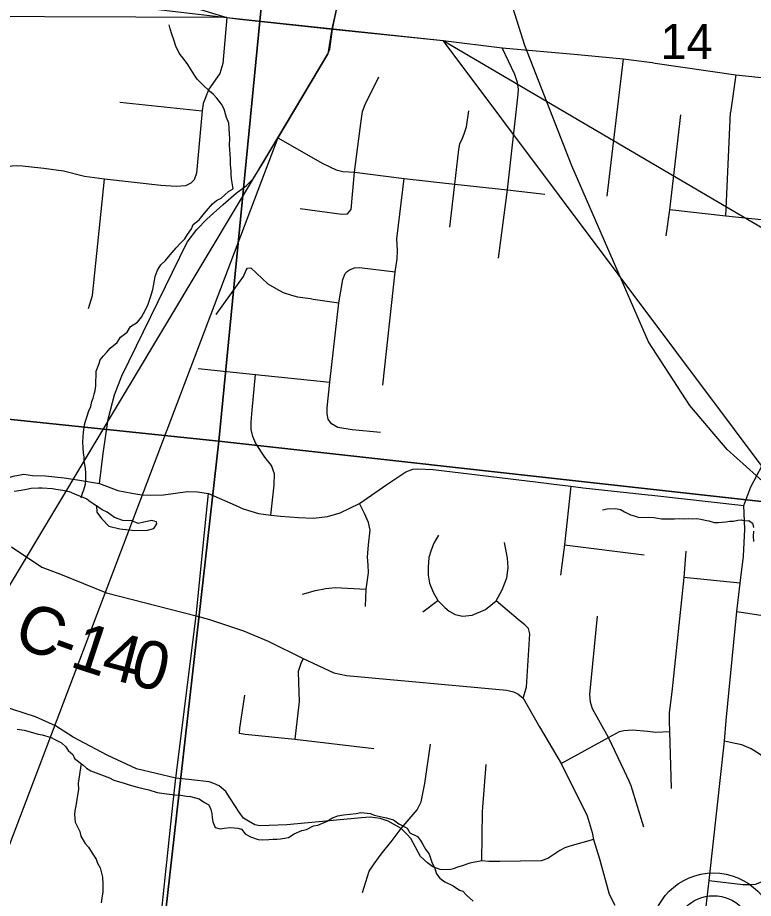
# Model space of a CAD drawing. Extents: x 0 to 34, y 0 to 22.
# Drawn here: x 6.604 to 7.479, y 17.836 to 18.884 of the extents above; entities that cross this region are included whole.
import ezdxf

# ---------------------------------------------------------------- set-up
doc = ezdxf.new("R2010")
doc.units = 0
for name, color, linetype in [('GM_X_City_Street', 7, 'Continuous'), ('GM_X_Corporation', 7, 'Continuous'), ('GM_X_County_Road', 7, 'Continuous'), ('GM_X_County_Road_Text', 7, 'Continuous'), ('GM_X_Minor_Lake', 7, 'Continuous'), ('GM_X_Minor_River', 7, 'Continuous'), ('GM_X_Rail_Line', 7, 'Continuous'), ('GM_X_Section_Text', 7, 'Continuous'), ('GM_X_Township_Road', 7, 'Continuous'), ('GM_X_Unincorporated', 7, 'Continuous'), ('SH_Text', 7, 'Continuous')]:
    doc.layers.add(name, color=color, linetype=linetype)

msp = doc.modelspace()

# ---------------------------------------------------------------- linework, layer by layer
at = {"layer": 'GM_X_City_Street'}
msp.add_line((7.4583, 18.8156), (7.4518, 18.7707), dxfattribs=at)
at = {"layer": 'GM_X_Corporation'}
for points in [[(5.9616, 19.4927), (6.9413, 19.3834), (6.8431, 18.3799), (5.8893, 18.4792)], [(7.955, 19.3167), (7.9506, 19.2737), (7.8526, 18.2675), (6.8431, 18.3799), (6.9413, 19.3834), (7.3067, 19.3446), (7.3077, 19.388)], [(6.8431, 18.3799), (6.7271, 17.3517), (5.7989, 17.4561), (5.8893, 18.4792)], [(6.8431, 18.3799), (7.8526, 18.2675), (7.7575, 17.2431), (6.7271, 17.3517)]]:
    msp.add_lwpolyline(points, close=True, dxfattribs=at)
at = {"layer": 'GM_X_County_Road'}
for points in [[(6.2648, 18.9452), (6.2762, 18.9441), (6.4455, 18.9279), (6.51, 18.9217), (6.5147, 18.9212), (6.6008, 18.9124), (6.6536, 18.9063), (6.701, 18.9016), (6.7946, 18.8905), (6.8528, 18.8836), (6.8619, 18.8825)], [(6.9786, 18.8699), (6.9921, 18.934), (6.9936, 18.9529)], [(6.8619, 18.8825), (6.8683, 18.8818), (6.9786, 18.8699)], [(6.7012, 18.3295), (6.7057, 18.3652), (6.7115, 18.4061), (6.7189, 18.4349), (6.7276, 18.4573), (6.8057, 18.6164), (6.8169, 18.6316), (6.829, 18.6437), (6.8485, 18.6613), (6.8638, 18.6749), (6.8758, 18.6836), (6.884, 18.6917), (6.8964, 18.7118), (6.9134, 18.7405), (6.9727, 18.8404), (6.9751, 18.846), (6.9786, 18.8699)], [(6.9786, 18.8699), (7.1101, 18.8565), (7.1805, 18.8478), (7.2702, 18.8398), (7.3244, 18.8344), (7.3587, 18.8301), (7.3625, 18.8296)], [(7.3625, 18.8296), (7.4583, 18.8156), (7.5834, 18.8023), (7.5901, 18.8016), (7.6544, 18.7948)], [(7.4678, 18.3034), (7.4763, 18.3256), (7.4897, 18.3507), (7.4923, 18.3553), (7.5228, 18.4144)], [(6.8309, 18.3175), (6.8627, 18.3036), (6.8723, 18.2993), (6.8902, 18.2939), (6.9051, 18.2918), (6.9167, 18.2904), (6.9378, 18.2889), (6.9557, 18.2881), (6.9725, 18.2901), (6.9877, 18.2946), (7.0104, 18.3055), (7.0431, 18.3284), (7.0656, 18.3432), (7.0741, 18.3464), (7.0794, 18.347), (7.0983, 18.346), (7.2329, 18.3296)], [(6.5051, 18.295), (6.5635, 18.3256), (6.584, 18.3334), (6.5984, 18.3381), (6.6113, 18.3404), (6.6216, 18.339), (6.6371, 18.3387), (6.6592, 18.3361), (6.6751, 18.3338), (6.7012, 18.3295)], [(6.7012, 18.3295), (6.7231, 18.3211), (6.7397, 18.3178), (6.7514, 18.3161), (6.7624, 18.3154), (6.7775, 18.3161), (6.8058, 18.3198), (6.8179, 18.3196), (6.8309, 18.3175)], [(7.2329, 18.3296), (7.2387, 18.3289), (7.262, 18.3261), (7.2766, 18.3243), (7.3541, 18.3158)], [(6.755, 17.6085), (6.7645, 17.693), (6.7721, 17.7924), (6.7884, 17.9468), (6.7919, 17.9787), (6.8164, 18.1721), (6.8285, 18.2944), (6.8309, 18.3175)], [(7.3541, 18.3158), (7.3582, 18.3154), (7.4678, 18.3034)], [(7.4132, 17.5855), (7.4215, 17.6597), (7.4203, 17.7001), (7.4178, 17.7283), (7.4167, 17.7471), (7.4194, 17.7953), (7.4265, 17.857), (7.4448, 18.0229), (7.4467, 18.0474), (7.4597, 18.177), (7.4634, 18.2109), (7.4675, 18.2429), (7.469, 18.2749), (7.4678, 18.3034)], [(6.5963, 18.2539), (6.6325, 18.2298), (6.6546, 18.2214), (6.7095, 18.1993), (6.8164, 18.1721), (6.8321, 18.1677), (6.8724, 18.154), (6.902, 18.142), (6.9436, 18.1213), (6.9801, 18.104), (6.9951, 18.1009), (7.186, 18.0837), (7.1939, 18.0817), (7.1991, 18.079), (7.2053, 18.0741), (7.2249, 18.0398), (7.2504, 17.9963), (7.2813, 17.9341), (7.2875, 17.9142), (7.289, 17.9061), (7.296, 17.8829), (7.3076, 17.8408), (7.3144, 17.8278)]]:
    msp.add_lwpolyline(points, dxfattribs=at)
at = {"layer": 'GM_X_Minor_Lake'}
for points in [[(6.6976, 18.3028), (6.6979, 18.2954), (6.7034, 18.2877), (6.7123, 18.2787), (6.7255, 18.2753), (6.7433, 18.2733), (6.7585, 18.274), (6.7658, 18.2758), (6.7694, 18.2814), (6.769, 18.2836), (6.7634, 18.2853), (6.7538, 18.2833)], [(6.7538, 18.2833), (6.7473, 18.2819), (6.7398, 18.2848), (6.7288, 18.2855), (6.719, 18.2888), (6.7104, 18.2951), (6.7044, 18.2979), (6.6976, 18.3028)]]:
    msp.add_lwpolyline(points, dxfattribs=at)
at = {"layer": 'GM_X_Minor_River'}
for points in [[(6.8583, 18.692), (6.8578, 18.697), (6.8579, 18.7012), (6.857, 18.7084), (6.8572, 18.7149), (6.8567, 18.7217), (6.8561, 18.7263), (6.8559, 18.7324), (6.8562, 18.7396), (6.856, 18.745), (6.8555, 18.7518), (6.8549, 18.7579), (6.8525, 18.7648), (6.8494, 18.7745), (6.8462, 18.7807), (6.8408, 18.7877), (6.8364, 18.7924), (6.8319, 18.796), (6.8242, 18.8038), (6.8176, 18.8105), (6.8144, 18.8152), (6.8104, 18.8214), (6.8054, 18.8292), (6.8003, 18.8358), (6.7959, 18.8413), (6.792, 18.8498), (6.7896, 18.8571), (6.7872, 18.864), (6.7851, 18.8702), (6.784, 18.875)], [(6.6793, 18.3124), (6.681, 18.3177), (6.6827, 18.3218), (6.6844, 18.3286), (6.6851, 18.3358), (6.6849, 18.3411), (6.6847, 18.3476), (6.6831, 18.356), (6.6829, 18.361), (6.6823, 18.3655), (6.6818, 18.3724), (6.6812, 18.3785), (6.6818, 18.3849), (6.682, 18.3903), (6.6834, 18.3993), (6.6847, 18.4035), (6.686, 18.4084), (6.6886, 18.4159), (6.6907, 18.4211), (6.692, 18.4268), (6.6937, 18.4309), (6.695, 18.4358), (6.6959, 18.44), (6.6968, 18.4456), (6.6974, 18.4631), (6.7008, 18.4721), (6.7021, 18.4766), (6.706, 18.4814), (6.71, 18.4855), (6.7139, 18.4903), (6.7221, 18.4972), (6.7262, 18.5035), (6.7343, 18.5093), (6.738, 18.516), (6.7465, 18.5214), (6.7513, 18.5274), (6.7558, 18.536), (6.759, 18.5427), (6.762, 18.5509), (6.7646, 18.56), (6.7659, 18.5664), (6.7665, 18.5709), (6.7674, 18.5755), (6.7703, 18.5833), (6.7743, 18.5897), (6.7798, 18.5948), (6.7834, 18.5989), (6.7877, 18.604), (6.7925, 18.6099), (6.7972, 18.6147), (6.8027, 18.6206), (6.8059, 18.6254), (6.8107, 18.6325), (6.8128, 18.6374), (6.8198, 18.6432), (6.8262, 18.651), (6.8357, 18.662), (6.8404, 18.6661), (6.8458, 18.6689), (6.8505, 18.6729), (6.8548, 18.6766), (6.8602, 18.6798), (6.8583, 18.692)], [(6.5998, 18.3201), (6.6079, 18.3214), (6.6144, 18.3227), (6.6197, 18.324), (6.6288, 18.3244), (6.633, 18.3243), (6.6451, 18.3235), (6.6493, 18.3226), (6.6576, 18.3215), (6.6651, 18.3198), (6.6741, 18.316), (6.6812, 18.3131), (6.6861, 18.3111), (6.6902, 18.3079), (6.6957, 18.3043), (6.6976, 18.3028)], [(7.2995, 18.2982), (7.3052, 18.2992), (7.3151, 18.2997), (7.3211, 18.2984), (7.326, 18.2956), (7.3331, 18.2923), (7.3373, 18.291), (7.3422, 18.2894), (7.3608, 18.2889), (7.3657, 18.2883), (7.3699, 18.2875), (7.3764, 18.2873), (7.3855, 18.2874), (7.3912, 18.2876), (7.3977, 18.2875), (7.4019, 18.2877), (7.4068, 18.2872), (7.4117, 18.2878), (7.4167, 18.2869), (7.422, 18.2856), (7.4261, 18.2848), (7.4325, 18.2831), (7.4375, 18.2829), (7.442, 18.2835), (7.4466, 18.2838), (7.4512, 18.2844), (7.4554, 18.2847), (7.4607, 18.2857), (7.4649, 18.2863), (7.4691, 18.2851), (7.4737, 18.2853), (7.4781, 18.2822), (7.4795, 18.2772)], [(7.4794, 18.2726), (7.4789, 18.2669), (7.4795, 18.2604)], [(6.6034, 18.0372), (6.6117, 18.0358), (6.6158, 18.0349), (6.6282, 18.0314), (6.6331, 18.0305), (6.6436, 18.0271), (6.6481, 18.025), (6.6559, 18.0209), (6.6611, 18.0162), (6.664, 18.0119), (6.6695, 18.0072), (6.6716, 18.0021), (6.6812, 17.9946), (6.6857, 17.9906), (6.6909, 17.9874), (6.7036, 17.9828), (6.713, 17.9794), (6.7182, 17.9766), (6.7306, 17.9731), (6.7355, 17.9714), (6.7422, 17.9693), (6.7479, 17.9676), (6.7599, 17.9649), (6.7697, 17.9619), (6.7754, 17.9609), (6.7844, 17.9598), (6.7909, 17.9592), (6.7981, 17.9586), (6.8049, 17.9576), (6.8094, 17.9571), (6.8199, 17.9541), (6.8262, 17.95), (6.8311, 17.9472), (6.8335, 17.9414), (6.8349, 17.9368), (6.8351, 17.9322), (6.8361, 17.9269), (6.8389, 17.9203), (6.8449, 17.9186), (6.8495, 17.9192), (6.8571, 17.9201), (6.8658, 17.9194), (6.8703, 17.9181), (6.8747, 17.9126), (6.881, 17.909), (6.89, 17.906), (6.8946, 17.9055), (6.9026, 17.906), (6.9079, 17.9062), (6.9121, 17.9064), (6.9166, 17.9066), (6.9262, 17.9082), (6.9328, 17.9125), (6.942, 17.9168), (6.9474, 17.9177), (6.9559, 17.922)], [(6.6792, 17.9962), (6.6759, 17.9731), (6.6761, 17.9655), (6.6755, 17.961), (6.6731, 17.9458), (6.6718, 17.9402), (6.6716, 17.9356), (6.6724, 17.9265), (6.6777, 17.9153), (6.6791, 17.9099), (6.6841, 17.901), (6.6881, 17.8967), (6.6924, 17.8897), (6.6971, 17.8827), (6.6988, 17.8777), (6.7021, 17.8722), (6.7047, 17.8611), (6.7052, 17.8527), (6.7053, 17.8436), (6.7039, 17.8361), (6.7033, 17.8304)], [(6.9559, 17.922), (6.9608, 17.923), (6.9712, 17.9272), (6.9786, 17.9315), (6.9848, 17.9339), (6.9916, 17.9352), (7.0065, 17.937), (7.0122, 17.9379), (7.0236, 17.9367), (7.0281, 17.9347), (7.0386, 17.9324), (7.0428, 17.9315), (7.0511, 17.9293), (7.0573, 17.9246), (7.0674, 17.9193), (7.0706, 17.9138), (7.0796, 17.9093), (7.0832, 17.9046), (7.0861, 17.9), (7.089, 17.8946), (7.0933, 17.8883), (7.0954, 17.8826), (7.0971, 17.8776), (7.0996, 17.8725), (7.102, 17.8652), (7.106, 17.8601), (7.1119, 17.8554), (7.122, 17.8508), (7.1294, 17.8457), (7.1335, 17.8444), (7.1379, 17.8397), (7.1457, 17.8325)]]:
    msp.add_lwpolyline(points, dxfattribs=at)
at = {"layer": 'GM_X_Rail_Line'}
msp.add_lwpolyline([(7.4939, 18.3285), (7.448, 18.3697), (7.4037, 18.422), (7.3546, 18.4981), (7.2632, 18.7074), (7.2074, 18.8505), (7.1644, 18.9863)], dxfattribs=at)
at = {"layer": 'GM_X_Township_Road'}
for p, q in [((7.3244, 18.8344), (7.3047, 18.6713)), ((6.7255, 18.783), (6.8234, 18.7729)), ((7.4464, 18.6474), (7.4518, 18.7707)), ((6.9553, 18.5488), (6.9859, 18.5444)), ((7.2545, 18.2564), (7.3493, 18.2444)), ((7.4634, 18.2109), (7.3964, 18.2175)), ((7.0858, 18.1769), (7.1036, 18.1903)), ((7.4597, 18.177), (7.5192, 18.1681))]:
    msp.add_line(p, q, dxfattribs=at)
for points in [[(6.8528, 18.8836), (6.848, 18.8289), (6.8445, 18.8173), (6.8311, 18.7986), (6.8245, 18.7814), (6.8234, 18.7729), (6.8166, 18.6987), (6.8137, 18.6908), (6.8098, 18.6866), (6.8035, 18.6833)], [(6.6167, 18.706), (6.6095, 18.7068), (6.6026, 18.7071), (6.597, 18.7068), (6.5801, 18.7033), (6.5706, 18.7013), (6.5478, 18.7019), (6.5412, 18.7032), (6.5388, 18.7073), (6.5397, 18.717), (6.5458, 18.7785), (6.5514, 18.8563)], [(7.1761, 18.5976), (7.1865, 18.6787), (7.1993, 18.7926), (7.1997, 18.7983), (7.1987, 18.8063), (7.1952, 18.8158), (7.1805, 18.8478)], [(6.9401, 18.6564), (6.9895, 18.6498), (6.9964, 18.65), (7.0005, 18.6555), (7.0045, 18.6996), (7.0125, 18.7608), (7.0143, 18.772), (7.0173, 18.7804), (7.0336, 18.8132)], [(7.1181, 18.6345), (7.1241, 18.6854), (7.1286, 18.7267), (7.13, 18.7334), (7.133, 18.7401), (7.1351, 18.7453), (7.1379, 18.7537), (7.1408, 18.7728)], [(7.3756, 18.624), (7.38, 18.6551), (7.3929, 18.768)], [(6.9134, 18.7405), (6.9671, 18.71), (6.9829, 18.7025), (6.9908, 18.7007), (7.0045, 18.6996), (7.0636, 18.6923), (7.1241, 18.6854), (7.1865, 18.6787), (7.2311, 18.6736)], [(6.8035, 18.6833), (6.7924, 18.6826), (6.7742, 18.6838), (6.7072, 18.6916), (6.6833, 18.6945), (6.6583, 18.7008), (6.635, 18.704), (6.6167, 18.706)], [(7.0384, 18.4462), (7.0531, 18.581), (7.0553, 18.5961), (7.0557, 18.6064), (7.0551, 18.6205), (7.0636, 18.6923)], [(6.6883, 18.5374), (6.693, 18.5532), (6.7072, 18.6916)], [(7.5895, 18.6632), (7.5532, 18.6427), (7.544, 18.6393), (7.5346, 18.6378), (7.519, 18.6398), (7.4464, 18.6474), (7.38, 18.6551)], [(6.8402, 18.5303), (6.8725, 18.5757), (6.8752, 18.5825), (6.8774, 18.5857), (6.8811, 18.5861), (6.9016, 18.5669), (6.9119, 18.5608), (6.9198, 18.5568), (6.9296, 18.5535), (6.9368, 18.5513), (6.9522, 18.5493), (6.9553, 18.5488)], [(7.0356, 18.3901), (7.0018, 18.3933), (6.9848, 18.3961), (6.9774, 18.4002), (6.9732, 18.4059), (6.9719, 18.4121), (6.9721, 18.4196), (6.9754, 18.4501), (6.9859, 18.5444), (6.9907, 18.5722), (6.9935, 18.5792), (6.9958, 18.5817), (6.9995, 18.584), (7.0047, 18.5861), (7.0104, 18.5864), (7.0531, 18.581)], [(6.8186, 18.466), (6.8868, 18.4589), (6.9754, 18.4501)], [(6.9051, 18.2918), (6.9092, 18.3275), (6.9093, 18.3407), (6.9057, 18.351), (6.898, 18.3606), (6.8873, 18.377), (6.8837, 18.3854), (6.8817, 18.3935), (6.8815, 18.4024), (6.8827, 18.4165), (6.8868, 18.4589)], [(7.262, 18.3261), (7.2545, 18.2564), (7.2496, 18.2203)], [(7.0176, 18.1831), (7.0183, 18.2036), (7.0212, 18.2232), (7.021, 18.2326), (7.0199, 18.2418), (7.0211, 18.2565), (7.0234, 18.274), (7.0213, 18.2832), (7.0164, 18.2937), (7.0104, 18.3055)], [(7.1044, 18.2681), (7.0989, 18.2583), (7.0957, 18.2502), (7.0932, 18.2415), (7.0924, 18.2298), (7.0924, 18.2204), (7.0938, 18.2107), (7.0982, 18.2001), (7.1036, 18.1903), (7.1122, 18.1818), (7.1173, 18.1776), (7.1242, 18.1736), (7.133, 18.1717), (7.1448, 18.1726), (7.1605, 18.1794), (7.1733, 18.1897), (7.1804, 18.2028), (7.1857, 18.217), (7.1874, 18.2296), (7.1868, 18.2405), (7.1832, 18.2594)], [(7.3988, 18.249), (7.3964, 18.2175), (7.3825, 18.0852)], [(6.9426, 18.1979), (6.9583, 18.2023), (6.9705, 18.2046), (6.9815, 18.2058), (7.0183, 18.2036)], [(7.2071, 18.1611), (7.2058, 18.1623), (7.1994, 18.1678), (7.1733, 18.1897)], [(7.3067, 18.0271), (7.2878, 18.0612), (7.2854, 18.0694), (7.2848, 18.0785), (7.2938, 18.1717)], [(7.2053, 18.0741), (7.2091, 18.0871), (7.2131, 18.1507), (7.2117, 18.1568), (7.2071, 18.1611)], [(6.7919, 17.9787), (6.7451, 17.99), (6.7104, 18.0063), (6.6697, 18.0278), (6.6489, 18.041), (6.6251, 18.0518), (6.5833, 18.0654), (6.5602, 18.0721), (6.5496, 18.0774), (6.5357, 18.0871), (6.5251, 18.0987), (6.5141, 18.112), (6.4991, 18.1289), (6.4833, 18.1471)], [(6.9436, 18.1213), (6.9407, 18.1154), (6.9374, 18.1056), (6.9378, 18.0927), (6.9386, 18.07), (6.9337, 18.0251)], [(7.3825, 18.0852), (7.3808, 18.0689), (7.3792, 18.0568), (7.3789, 18.0469), (7.3793, 18.0342), (7.3815, 17.9665)], [(6.8738, 18.0778), (6.8679, 18.0384), (6.8673, 18.0325), (6.8744, 18.0313), (6.9337, 18.0251), (7.0277, 18.0142)], [(7.2504, 17.9963), (7.3067, 18.0271), (7.32, 18.0342), (7.3249, 18.0357), (7.3355, 18.0362), (7.3532, 18.0346), (7.3633, 18.0336), (7.3793, 18.0342)], [(7.3488, 17.9205), (7.3337, 17.9697), (7.3315, 17.9754), (7.326, 17.9873), (7.3067, 18.0271)], [(7.4265, 17.857), (7.4665, 17.8524), (7.4748, 17.8523), (7.4819, 17.8528), (7.4909, 17.8563), (7.4995, 17.862), (7.5046, 17.8662), (7.5083, 17.8719), (7.5114, 17.8798), (7.5118, 17.883), (7.5145, 17.8989), (7.5176, 17.9273), (7.5188, 17.9448), (7.5182, 17.9522), (7.5166, 17.962), (7.5136, 17.9726), (7.5097, 17.9816), (7.502, 17.9924), (7.4956, 17.9998), (7.4873, 18.007), (7.4767, 18.0138), (7.4653, 18.0184), (7.4555, 18.0207), (7.4448, 18.0229)], [(7.0478, 17.9026), (7.0484, 17.9033), (7.06, 17.9188), (7.0793, 17.9411), (7.084, 17.9507), (7.0881, 17.9726), (7.0952, 18.0195)], [(7.1562, 17.8807), (7.1571, 17.9392), (7.1611, 17.9951)], [(7.1172, 17.87), (7.1064, 17.8702), (7.0977, 17.8735), (7.0914, 17.8782), (7.0833, 17.8857), (7.0718, 17.9069), (7.0666, 17.9127), (7.06, 17.9188), (7.0512, 17.9243), (7.0448, 17.9279), (7.0352, 17.9309), (7.0232, 17.9323), (7.0131, 17.9316), (6.924, 17.9235), (6.9029, 17.9226), (6.8919, 17.9223), (6.8859, 17.9235), (6.8784, 17.9276), (6.8724, 17.9312), (6.8675, 17.9385), (6.857, 17.9543), (6.8514, 17.9632), (6.8434, 17.9699), (6.8373, 17.9727), (6.8318, 17.9745), (6.8106, 17.9769), (6.7919, 17.9787)], [(7.289, 17.9061), (7.2608, 17.8979), (7.2549, 17.8959), (7.2489, 17.8929), (7.2348, 17.8834), (7.2269, 17.8804), (7.2023, 17.8803), (7.1774, 17.8799), (7.1646, 17.8796), (7.1562, 17.8807), (7.1418, 17.8777), (7.1316, 17.8743), (7.1271, 17.8728)], [(7.014, 17.8427), (7.0221, 17.8683), (7.0279, 17.8771), (7.0363, 17.8884), (7.0478, 17.9026)], [(7.1271, 17.8728), (7.1226, 17.8712), (7.1172, 17.87)]]:
    msp.add_lwpolyline(points, dxfattribs=at)
at = {"layer": 'GM_X_Unincorporated'}
for radius in [0.0744, 0.0472]:
    msp.add_circle((7.4318, 17.7918), radius, dxfattribs=at)
at = {"layer": 'SH_Text'}
msp.add_line((6.8528, 18.8836), (7.1101, 18.8565), dxfattribs=at)
for points in [[(5.117, 19.4095), (6.8528, 18.8836), (5.117, 18.89)], [(7.8046, 17.9295), (7.1101, 18.8565), (7.8046, 18.4489)], [(6.3738, 17.841), (6.9134, 18.7405), (6.3738, 17.3215)]]:
    msp.add_lwpolyline(points, close=True, dxfattribs=at)
msp.add_lwpolyline([(6.9921, 18.934), (6.9776, 18.8701), (6.9727, 18.8404), (6.9134, 18.7405)], dxfattribs=at)

# ---------------------------------------------------------------- texts
at = {"layer": 'GM_X_County_Road_Text'}
for s, rotation, p in [('C', 338.5772, (6.5963, 18.1382)), ('1', 341.7118, (6.6643, 18.1123)), ('4', 345.175, (6.7009, 18.1003)), ('-', 339.9977, (6.6409, 18.1208)), ('0', 345.7322, (6.735, 18.0913))]:
    msp.add_text(s, height=0.0568, rotation=rotation, dxfattribs=at).set_placement(p)
at = {"layer": 'GM_X_Section_Text'}
msp.add_text('14', height=0.04186, rotation=0, dxfattribs=at).set_placement((7.3685, 18.8343))

doc.saveas('drawing.dxf')
